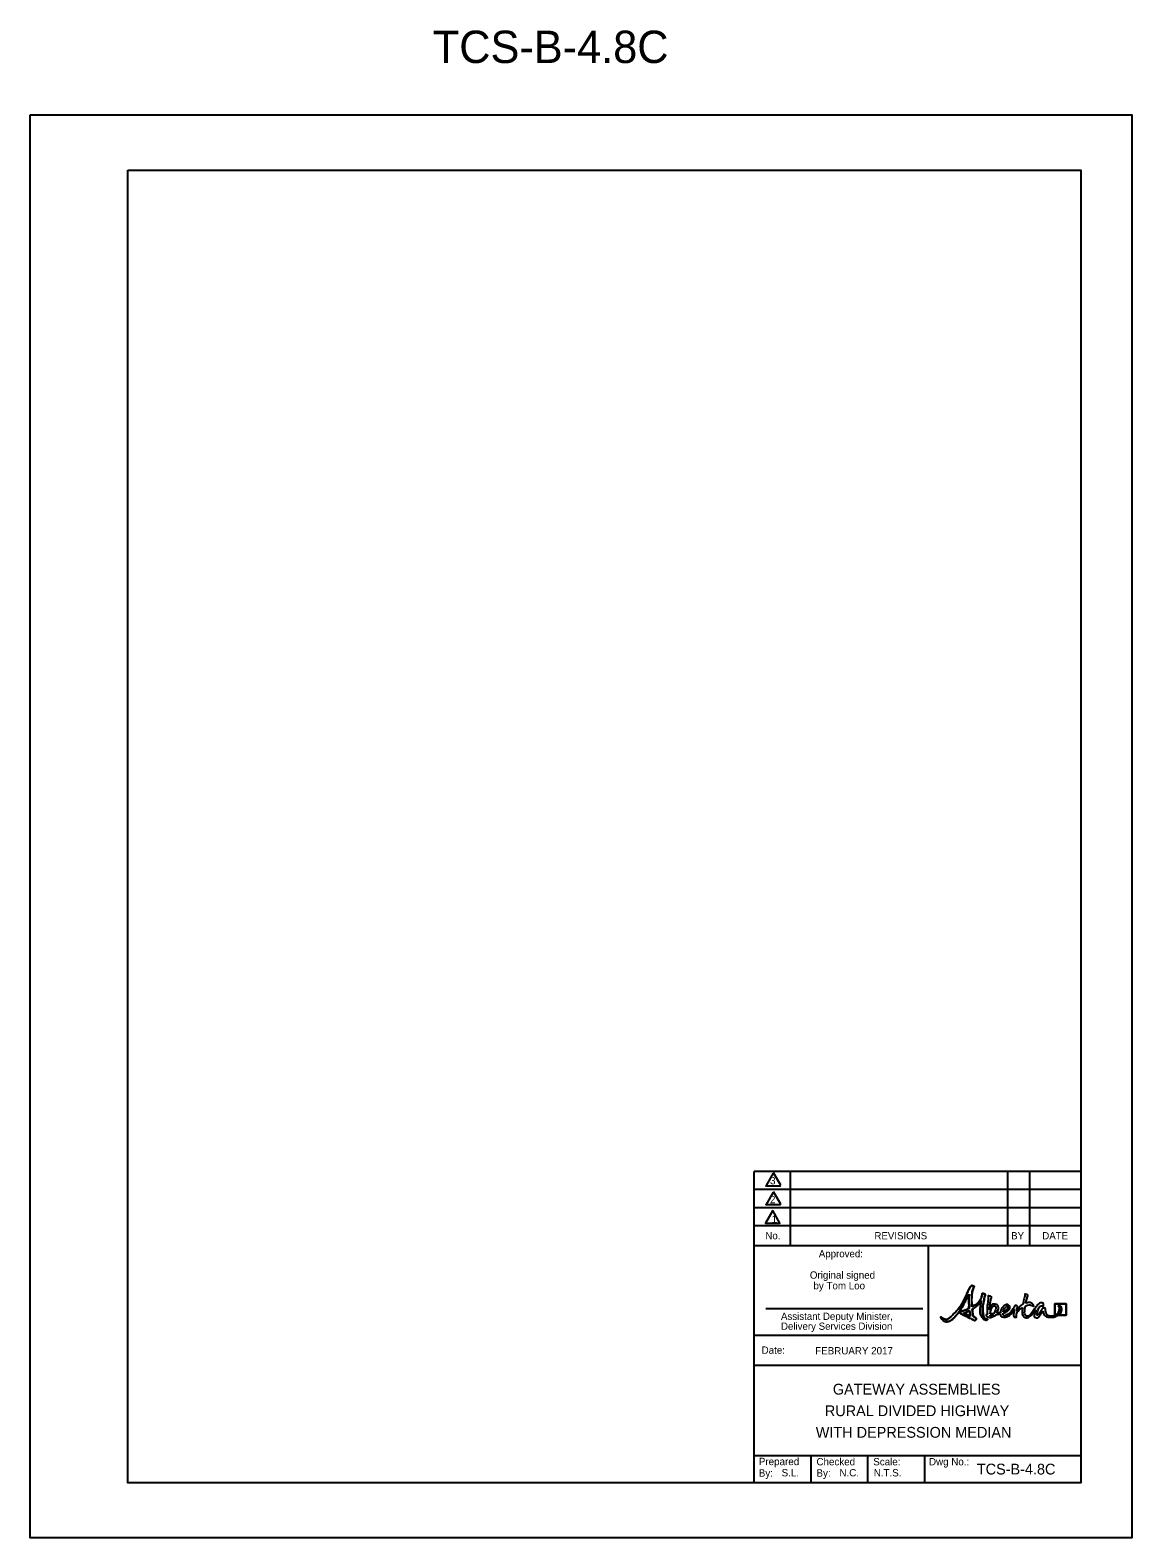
# Model space of a CAD drawing. Extents: x 1535 to 2422, y 125 to 421.
# Drawn here: x 2206.3 to 2422.3, y 125 to 420.6 of the extents above; entities that cross this region are included whole.
import ezdxf

# ---------------------------------------------------------------- set-up
doc = ezdxf.new("R2010")
doc.units = 0
for name, color, linetype in [('Level 1', 7, 'Continuous'), ('Level 10', 7, 'Continuous'), ('Level 2', 7, 'Continuous'), ('Level 22', 7, 'Continuous'), ('Level 44', 7, 'Continuous'), ('Level 53', 7, 'Continuous'), ('Level 60', 7, 'Continuous')]:
    doc.layers.add(name, color=color, linetype=linetype)

msp = doc.modelspace()

# ---------------------------------------------------------------- linework, layer by layer
at = {"layer": 'Level 1'}
for p, q in [((2412.14, 196.82), (2348.26, 196.82)), ((2412.14, 193.27), (2348.26, 193.27)), ((2412.14, 189.72), (2348.26, 189.72)), ((2412.14, 186.18), (2348.26, 186.18)), ((2348.26, 135.79), (2348.26, 182.27)), ((2348.26, 182.27), (2412.14, 182.27)), ((2382.33, 182.27), (2382.33, 158.85)), ((2348.26, 164.71), (2382.33, 164.71)), ((2348.26, 158.85), (2412.14, 158.85)), ((2348.26, 141.11), (2412.14, 141.11)), ((2359.4, 135.79), (2359.4, 141.11)), ((2370.54, 135.79), (2370.54, 141.11)), ((2381.67, 141.11), (2381.67, 135.79))]:
    msp.add_line(p, q, dxfattribs=at)
msp.add_lwpolyline([(2351.88, 189.16), (2350.47, 186.69), (2353.3, 186.69)], close=True, dxfattribs=at)
at = {"layer": 'Level 2'}
msp.add_line((2382.33, 182.27), (2382.33, 182.27), dxfattribs=at)
at = {"layer": 'Level 22'}
msp.add_line((2363.75, 135.79), (2363.75, 135.79), dxfattribs=at)
at = {"layer": 'Level 53'}
msp.add_line((2407.82, 168.64), (2407.27, 168.64), dxfattribs=at)
msp.add_lwpolyline([(2407.82, 168.64), (2409.43, 168.64), (2409.43, 170.87), (2407.2, 170.87), (2407.2, 168.64), (2407.27, 168.64)], dxfattribs=at)
for points, degree in [([(2393.83, 167.83), (2393.59, 167.87), (2393.28, 168.19), (2393.18, 168.73), (2393.01, 169.7), (2393.11, 170.65), (2393.4, 172.07), (2393.45, 172.34), (2393.63, 172.8), (2393.05, 172.89), (2392.87, 172.92), (2392.96, 172.83), (2392.91, 172.59), (2392.69, 171.53), (2391.82, 170.76), (2390.95, 170.25), (2390.86, 171.46), (2390.9, 172.81), (2391.12, 173.64), (2391.32, 174.33), (2391.55, 174.2), (2391.26, 174.35), (2390.96, 174.5), (2390.64, 174.3), (2390.38, 173.78), (2390.12, 173.26), (2388.93, 170.45), (2387.01, 168.55), (2386.04, 167.57), (2385.15, 168.08), (2384.98, 168.22), (2384.83, 168.35), (2384.78, 168.16), (2384.96, 167.97), (2385.75, 167.11), (2386.9, 167.6), (2387.32, 168.02), (2388.49, 169.19), (2389.84, 171.69), (2390.39, 172.75), (2390.34, 172.15), (2390.32, 171.15), (2390.43, 169.97), (2389.84, 169.69), (2389.31, 169.52), (2389.06, 169.45), (2388.79, 169.38), (2388.62, 169.27), (2388.61, 169.14), (2388.61, 169.01), (2388.79, 168.89), (2389.05, 168.77), (2389.52, 168.54), (2390.89, 167.89), (2391.23, 167.7), (2391.52, 167.53), (2391.66, 167.66), (2391.75, 167.84), (2391.86, 168.08), (2391.55, 168.22), (2391.25, 168.3), (2391.14, 168.7), (2391.05, 169.24), (2390.99, 169.83), (2391.69, 170.26), (2392.37, 170.83), (2392.77, 171.54), (2392.67, 170.95), (2392.41, 168.92), (2393.05, 168.06), (2393.19, 167.87), (2393.51, 167.66), (2393.81, 167.69), (2393.95, 167.71), (2394.03, 167.8), (2394.01, 167.83), (2394, 167.86), (2393.92, 167.82), (2393.83, 167.83)], 3), ([(2390.95, 170.25), (2390.86, 171.46), (2390.9, 172.81), (2391.12, 173.64), (2391.32, 174.33), (2391.55, 174.2), (2391.26, 174.35), (2390.96, 174.5), (2390.64, 174.3), (2390.38, 173.78), (2390.12, 173.26), (2388.93, 170.45), (2387.01, 168.55), (2386.04, 167.57), (2385.15, 168.08), (2384.98, 168.22), (2384.83, 168.35), (2384.78, 168.16), (2384.96, 167.97), (2385.75, 167.11), (2386.9, 167.6), (2387.32, 168.02), (2388.49, 169.19), (2389.84, 171.69), (2390.39, 172.75)], 3), ([(2390.39, 172.75), (2390.34, 172.15), (2390.32, 171.15), (2390.43, 169.97)], 2), ([(2393.83, 167.83), (2393.59, 167.87), (2393.28, 168.19), (2393.18, 168.73), (2393.01, 169.7), (2393.11, 170.65), (2393.4, 172.07), (2393.45, 172.34), (2393.63, 172.8), (2393.05, 172.89), (2392.87, 172.92), (2392.96, 172.83), (2392.91, 172.59), (2392.69, 171.53), (2391.82, 170.76), (2390.95, 170.25)], 3), ([(2390.99, 169.83), (2391.69, 170.26), (2392.37, 170.83), (2392.77, 171.54)], 2), ([(2392.77, 171.54), (2392.67, 170.95), (2392.41, 168.92), (2393.05, 168.06), (2393.19, 167.87), (2393.51, 167.66), (2393.81, 167.69), (2393.95, 167.71), (2394.03, 167.8), (2394.01, 167.83), (2394, 167.86), (2393.92, 167.82), (2393.83, 167.83)], 3), ([(2394.37, 169.67), (2394.41, 170.24), (2394.51, 170.93), (2394.63, 171.58), (2394.69, 171.84), (2394.87, 172.31), (2394.29, 172.4), (2394.1, 172.43), (2394.13, 172.34), (2394.15, 172.09), (2394.17, 171.75), (2393.79, 169.71), (2393.99, 168.82)], 3), ([(2401.52, 171.01), (2401.59, 171.31), (2401.66, 171.61), (2401.75, 171.91), (2401.82, 172.17), (2402.04, 172.64), (2401.46, 172.73), (2401.28, 172.76), (2401.36, 172.67), (2401.3, 172.42), (2401.19, 171.96), (2401.05, 171.37), (2400.95, 170.78)], 3), ([(2390.43, 169.97), (2389.84, 169.69), (2389.31, 169.52), (2389.06, 169.45), (2388.79, 169.38), (2388.62, 169.27), (2388.61, 169.14), (2388.61, 169.01), (2388.79, 168.89), (2389.05, 168.77), (2389.52, 168.54), (2390.89, 167.89), (2391.23, 167.7), (2391.52, 167.53), (2391.66, 167.66), (2391.75, 167.84), (2391.86, 168.08), (2391.55, 168.22), (2391.25, 168.3)], 3), ([(2389.36, 169.04), (2389.67, 169.15), (2390.06, 169.32), (2390.48, 169.54)], 2), ([(2389.36, 169.04), (2389.67, 169.15), (2390.06, 169.32), (2390.48, 169.54), (2390.53, 169.06), (2390.59, 168.72), (2390.66, 168.47), (2390.36, 168.58), (2389.92, 168.75), (2389.36, 169.04)], 3), ([(2390.66, 168.47), (2390.36, 168.58), (2389.92, 168.75), (2389.36, 169.04)], 2), ([(2390.48, 169.54), (2390.53, 169.06), (2390.59, 168.72), (2390.66, 168.47)], 2), ([(2391.25, 168.3), (2391.14, 168.7), (2391.05, 169.24), (2390.99, 169.83)], 2), ([(2393.99, 168.82), (2393.74, 168.74), (2393.64, 168.55), (2393.96, 168.35), (2394.18, 168.21), (2394.67, 168.17), (2395.17, 168.41), (2395.34, 168.5), (2395.5, 168.62), (2395.63, 168.77)], 3), ([(2395.81, 169.01), (2396.22, 169.68), (2396.19, 170.59), (2395.58, 170.75), (2394.88, 170.92), (2394.52, 170.24), (2394.37, 169.67)], 3), ([(2394.44, 168.45), (2394.48, 168.48), (2394.5, 168.52), (2394.5, 168.56), (2394.5, 168.59), (2394.5, 168.63), (2394.5, 168.66)], 3), ([(2394.5, 168.66), (2394.62, 168.66), (2394.82, 168.68), (2395.05, 168.7)], 2), ([(2394.52, 168.88), (2394.61, 169.6), (2394.99, 170.59), (2395.45, 170.43), (2395.72, 170.34), (2395.58, 169.5), (2395.23, 168.94)], 3), ([(2395.23, 168.94), (2395.01, 168.92), (2394.77, 168.9), (2394.52, 168.88)], 2), ([(2395.05, 168.7), (2394.93, 168.57), (2394.79, 168.47), (2394.65, 168.45)], 2), ([(2395.63, 168.77), (2395.92, 168.8), (2396.23, 168.85), (2396.51, 168.91)], 2), ([(2396.51, 169.13), (2396.3, 169.08), (2396.07, 169.05), (2395.81, 169.01)], 2), ([(2397.03, 169.03), (2397.13, 169.06), (2397.21, 169.09), (2397.29, 169.13), (2398.17, 169.52), (2398.47, 170.11), (2398.25, 170.47), (2398.04, 170.81), (2397.43, 170.7), (2396.95, 170.2), (2396.71, 169.95), (2396.53, 169.52), (2396.51, 169.13)], 3), ([(2396.51, 168.91), (2396.56, 168.51), (2396.82, 168.21), (2397.41, 168.27), (2398.26, 168.35), (2399.01, 169.39), (2399.29, 169.89)], 3), ([(2399.71, 169.45), (2399.76, 169.72), (2399.85, 170.03), (2399.86, 170.24), (2399.86, 170.45), (2399.71, 170.5), (2399.66, 170.52), (2399.53, 170.55), (2399.38, 170.49), (2399.23, 170.28), (2398.87, 169.78), (2398.42, 168.99), (2397.75, 168.66), (2397.26, 168.43), (2397.04, 168.67), (2397.03, 169.03)], 3), ([(2397.5, 170.15), (2397.8, 170.43), (2397.95, 170.41), (2397.99, 170.33), (2398.07, 170.17), (2397.72, 169.61), (2397.06, 169.3)], 3), ([(2397.06, 169.3), (2397.11, 169.61), (2397.27, 169.94), (2397.5, 170.15)], 2), ([(2399.29, 169.89), (2399.24, 169.35), (2398.89, 168.18), (2399.49, 168.24), (2399.72, 168.26), (2399.62, 168.3), (2399.64, 168.5), (2399.69, 169.21), (2400.28, 169.81), (2400.86, 170.17)], 3), ([(2400.95, 170.78), (2400.47, 170.5), (2400.03, 170.05), (2399.71, 169.45)], 2), ([(2400.86, 170.17), (2400.76, 169.31), (2400.79, 168.54), (2401.18, 168.29), (2401.91, 167.84), (2402.93, 169.03), (2403.49, 169.75)], 3), ([(2406.58, 168.44), (2405.66, 168.44), (2405.43, 169.15), (2405.38, 169.51), (2405.35, 169.74), (2405.4, 170.08), (2405, 170.03), (2404.72, 170), (2404.46, 169.45), (2404.1, 168.99), (2403.79, 168.59), (2403.65, 168.63), (2403.73, 168.97), (2403.82, 169.4), (2404.17, 170.4), (2404.58, 170.47), (2404.77, 170.51), (2404.84, 170.18), (2404.93, 170.38), (2405.01, 170.59), (2404.93, 171.04), (2404.51, 171.04), (2404.21, 171.04), (2403.86, 170.73), (2403.57, 170.37), (2403.31, 170.06), (2402.03, 168.17), (2401.49, 168.57), (2401.24, 168.77), (2401.26, 169.54), (2401.41, 170.46)], 3), ([(2401.41, 170.46), (2402.05, 170.71), (2402.59, 170.62), (2402.89, 170.48), (2403.04, 170.41), (2403.06, 170.42), (2402.99, 170.58), (2402.9, 170.82), (2402.38, 171.2), (2401.58, 171.03), (2401.56, 171.02), (2401.54, 171.02), (2401.52, 171.01)], 3), ([(2403.49, 169.75), (2403.21, 169.11), (2403.04, 168.28), (2403.47, 168.16), (2403.98, 168.01), (2404.38, 168.85), (2404.84, 169.49)], 3), ([(2404.84, 169.49), (2404.9, 169.03), (2405.2, 168.23), (2406.44, 168.23), (2407, 168.23), (2407.47, 168.39), (2407.82, 168.64)], 3), ([(2407.27, 168.64), (2407.06, 168.52), (2406.83, 168.44), (2406.58, 168.44)], 2), ([(2407.2, 170.87), (2407.2, 170.87), (2407.2, 168.64), (2407.2, 168.64), (2407.2, 168.64), (2407.27, 168.64), (2407.27, 168.64), (2407.75, 168.93), (2408.08, 169.48), (2408.08, 169.94), (2408.08, 170.33), (2407.87, 170.31), (2407.89, 170.37), (2407.96, 170.53), (2408.45, 170.44), (2408.48, 169.88), (2408.5, 169.41), (2408.26, 168.95), (2407.82, 168.64), (2407.82, 168.64), (2409.43, 168.64), (2409.43, 168.64), (2409.43, 168.64), (2409.43, 170.87), (2409.43, 170.87), (2409.43, 170.87), (2407.2, 170.87), (2407.2, 170.87)], 3), ([(2407.27, 168.64), (2407.75, 168.93), (2408.08, 169.48), (2408.08, 169.94), (2408.08, 170.33), (2407.87, 170.31), (2407.89, 170.37), (2407.96, 170.53), (2408.45, 170.44), (2408.48, 169.88), (2408.5, 169.41), (2408.26, 168.95), (2407.82, 168.64)], 3), ([(2394.65, 168.45), (2394.56, 168.44), (2394.5, 168.44), (2394.44, 168.45)], 2)]:
    msp.add_open_spline(points, degree=degree, dxfattribs=at)
at = {"layer": 'Level 60'}
for p, q in [((2206.29, 403.98), (2206.29, 403.98)), ((2348.26, 190.35), (2348.26, 196.82)), ((2355.35, 190.35), (2355.35, 196.82)), ((2397.94, 196.82), (2397.94, 182.27)), ((2402.25, 196.82), (2402.25, 182.27)), ((2348.26, 182.27), (2348.26, 190.35)), ((2355.35, 182.27), (2355.35, 190.35)), ((2350.53, 169.95), (2381.34, 169.95)), ((2422.29, 124.98), (2422.29, 124.98))]:
    msp.add_line(p, q, dxfattribs=at)
for points in [[(2206.29, 403.98), (2422.29, 403.98), (2422.29, 124.98), (2206.29, 124.98)], [(2225.42, 393.17), (2412.29, 393.17), (2412.29, 135.79), (2225.42, 135.79)]]:
    msp.add_lwpolyline(points, close=True, dxfattribs=at)
for points in [[(2351.96, 196.49), (2350.57, 194.07)], [(2353.45, 194.14), (2352.05, 196.57)], [(2350.57, 194.07), (2350.54, 194.02), (2353.38, 194.02), (2353.36, 194.07)], [(2351.96, 192.78), (2350.57, 190.35)], [(2353.45, 190.43), (2352.05, 192.85)], [(2350.57, 190.35), (2350.54, 190.31), (2353.38, 190.31), (2353.36, 190.35)]]:
    msp.add_lwpolyline(points, dxfattribs=at)

# ---------------------------------------------------------------- texts
at = {"layer": 'Level 1'}
for s, height, p in [('3', 1.45, (2351.35, 194.29)), ('2', 1.45, (2351.34, 190.58)), ('1', 1.45, (2351.66, 186.75)), ('No.', 1.419, (2350.44, 183.51)), ('REVISIONS', 1.419, (2371.82, 183.51)), ('BY', 1.419, (2398.63, 183.51)), ('DATE', 1.419, (2404.73, 183.51)), ('Date:', 1.434, (2349.7, 161.07)), ('Prepared', 1.441, (2349.15, 139.23)), ('Checked', 1.434, (2360.46, 139.19)), ('Scale:', 1.434, (2371.6, 139.19)), ('Dwg No.:', 1.434, (2382.52, 139.19)), ('By:', 1.441, (2349.15, 136.97)), ('By:', 1.441, (2360.46, 136.97)), ('    N.T.S.   ', 1.4336, (2369.57, 137.02))]:
    msp.add_text(s, height=height, rotation=360, dxfattribs=at).set_placement(p)
at = {"layer": 'Level 10'}
for s, p in [('GATEWAY ASSEMBLIES', (2363.67, 153.07)), ('RURAL DIVIDED HIGHWAY ', (2362.1, 148.84)), ('WITH DEPRESSION MEDIAN', (2360.32, 144.61))]:
    msp.add_text(s, height=2.116, rotation=360, dxfattribs=at).set_placement(p)
at = {"layer": 'Level 44'}
msp.add_text('TCS-B-4.8C', height=6.348, rotation=360, dxfattribs=at).set_placement((2285.23, 414.16))
at = {"layer": 'Level 60'}
for s, height, p in [('Approved:', 1.419, (2360.92, 179.98)), ('Original signed', 1.434, (2359.16, 175.79)), ('by Tom Loo', 1.434, (2359.86, 173.71)), ('Assistant Deputy Minister,', 1.4194, (2353.5, 167.72)), ('Delivery Services Division', 1.4194, (2353.5, 165.77)), ('FEBRUARY 2017', 1.434, (2360.21, 160.95)), ('TCS-B-4.8C', 2.116, (2391.9, 137.4))]:
    msp.add_text(s, height=height, dxfattribs=at).set_placement(p)
for s, p in [('S.L.', (2353.63, 137.03)), ('N.C.', (2364.96, 137.03))]:
    msp.add_text(s, height=1.434, rotation=360, dxfattribs=at).set_placement(p)

doc.saveas('drawing.dxf')
